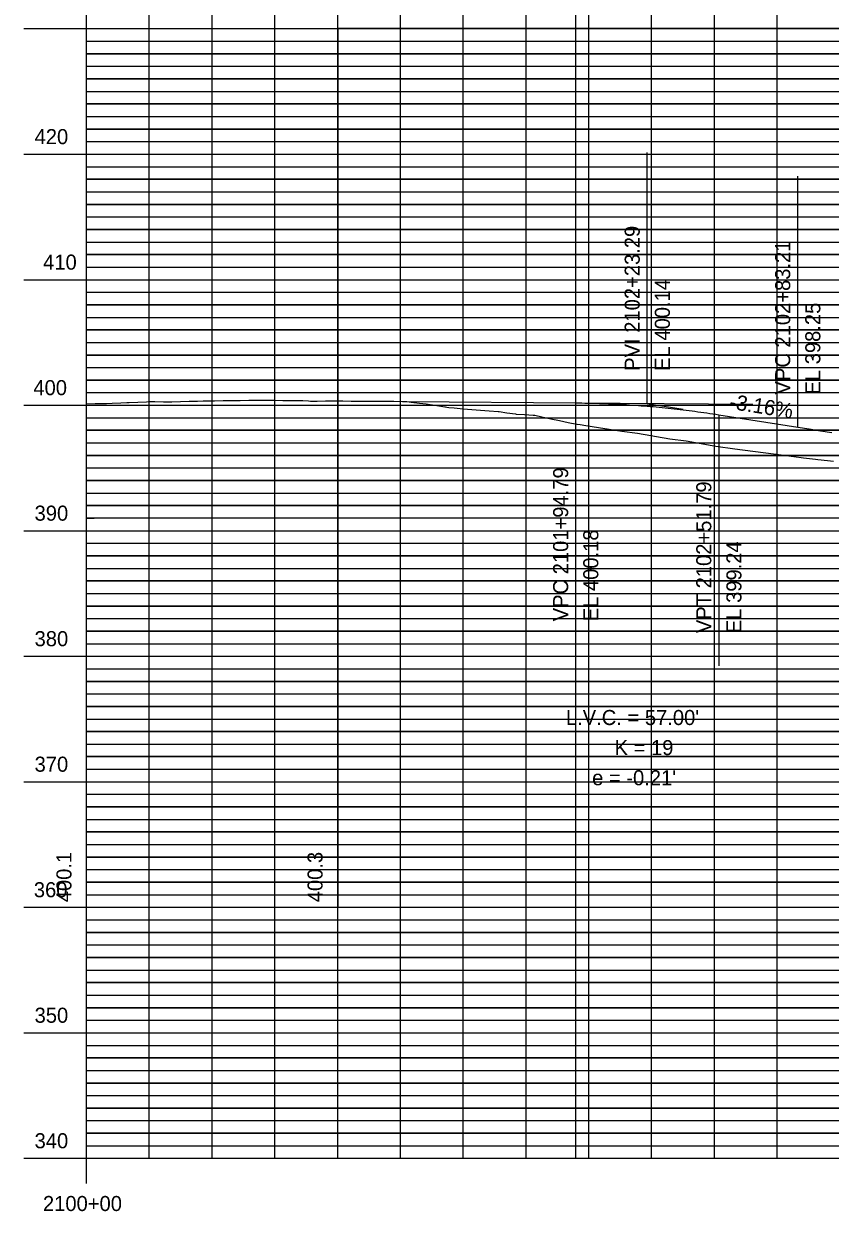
# Model space of a CAD drawing. Extents: x 1195880 to 1289360, y 2059330 to 2086925.
# Drawn here: x 1196947.8 to 1197268.9, y 2066770.1 to 2067243.1 of the extents above; entities that cross this region are included whole.
import ezdxf

# ---------------------------------------------------------------- set-up
doc = ezdxf.new("R2010")
doc.units = 0
for name, color, linetype in [('20', 7, 'Continuous'), ('41', 7, 'Continuous'), ('51', 7, 'Continuous'), ('Clip', 7, 'Continuous'), ('Default', 7, 'Continuous'), ('Existing Ground PGL', 7, 'Continuous'), ('Grid', 7, 'Continuous'), ('Grid Lables', 7, 'Continuous'), ('Profile', 7, 'Continuous'), ('Profile Annotation', 7, 'Continuous')]:
    doc.layers.add(name, color=color, linetype=linetype)

msp = doc.modelspace()

# ---------------------------------------------------------------- linework, layer by layer
at = {"layer": '20'}
msp.add_line((1197167.59, 2067092.07), (1197238.09, 2067091.52), dxfattribs=at)
at = {"layer": 'Clip'}
msp.add_lwpolyline([(1197072.8, 2066891.15), (1197672.8, 2066891.15), (1197672.8, 2067241.15), (1197072.8, 2067241.15)], close=True, dxfattribs=at)
at = {"layer": 'Default'}
for p, q in [((1197167.59, 2066791.15), (1197167.59, 2067423.97)), ((1196972.8, 2066791.15), (1197167.59, 2066791.15))]:
    msp.add_line(p, q, dxfattribs=at)
at = {"layer": 'Existing Ground PGL'}
msp.add_lwpolyline([(1196972.8, 2067091.71), (1196976.2, 2067091.78), (1196979.6, 2067091.82), (1196980.73, 2067091.84), (1196983, 2067091.96), (1196986.4, 2067092.12), (1196988.89, 2067092.24), (1196989.8, 2067092.28), (1196993.21, 2067092.42), (1196996.61, 2067092.55), (1196997.74, 2067092.58), (1197000.01, 2067092.57), (1197003.41, 2067092.54), (1197006.28, 2067092.51), (1197006.81, 2067092.53), (1197010.21, 2067092.65), (1197013.61, 2067092.76), (1197013.91, 2067092.77), (1197017.01, 2067092.82), (1197019.22, 2067092.85), (1197020.41, 2067092.88), (1197023.81, 2067092.96), (1197027.21, 2067093.03), (1197027.43, 2067093.03), (1197030.61, 2067093.05), (1197032.11, 2067093.06), (1197034.02, 2067093.08), (1197037.42, 2067093.11), (1197040.82, 2067093.12), (1197041.76, 2067093.12), (1197044.22, 2067093.11), (1197045.45, 2067093.1), (1197047.62, 2067093.1), (1197051.02, 2067093.08), (1197054.42, 2067093.06), (1197056.61, 2067093.04), (1197057.82, 2067093.02), (1197058.93, 2067093), (1197061.22, 2067092.86), (1197062.02, 2067092.8), (1197064.62, 2067092.82), (1197068.02, 2067092.83), (1197071.43, 2067092.83), (1197074.83, 2067092.83), (1197078.23, 2067092.82), (1197079.3, 2067092.81), (1197080.27, 2067092.81), (1197081.63, 2067092.81), (1197085.03, 2067092.79), (1197088.43, 2067092.76), (1197091.83, 2067092.73), (1197095.23, 2067092.7), (1197098.63, 2067092.65), (1197099.67, 2067092.64), (1197099.96, 2067092.62), (1197100.37, 2067092.61), (1197102.03, 2067092.41), (1197105.43, 2067092), (1197108.05, 2067091.67), (1197108.83, 2067091.55), (1197112.24, 2067091.03), (1197115.48, 2067090.54), (1197115.73, 2067090.5), (1197116.26, 2067090.43), (1197117.11, 2067090.29), (1197119.22, 2067090.09), (1197122.71, 2067089.76), (1197126.2, 2067089.44), (1197129.68, 2067089.14), (1197129.69, 2067089.14), (1197133.18, 2067088.89), (1197136.67, 2067088.65), (1197137.07, 2067088.63), (1197140.17, 2067088.18), (1197143.66, 2067087.69), (1197143.94, 2067087.65), (1197147.15, 2067087.42), (1197150.64, 2067087.19), (1197151.34, 2067087.15), (1197154.13, 2067086.52), (1197157.62, 2067085.77), (1197161.11, 2067085.03), (1197164.61, 2067084.32), (1197168.1, 2067083.62), (1197168.14, 2067083.62), (1197169.43, 2067083.47), (1197171.59, 2067083.12), (1197186.01, 2067080.83), (1197192.22, 2067080.08), (1197205.08, 2067077.78), (1197211.54, 2067076.92), (1197223.38, 2067074.86), (1197230.9, 2067073.84), (1197238.13, 2067072.87), (1197247.44, 2067071.65), (1197253.42, 2067070.85), (1197254.49, 2067070.71), (1197258.24, 2067070.23), (1197263.06, 2067069.66), (1197263.97, 2067069.55), (1197267.87, 2067069.12), (1197270.26, 2067068.88)], dxfattribs=at)
at = {"layer": 'Grid'}
for p, q in [((1196972.8, 2066791.15), (1196972.8, 2067391.15)), ((1196997.8, 2066791.15), (1196997.8, 2067391.15)), ((1197022.8, 2066791.15), (1197022.8, 2067391.15)), ((1197047.8, 2066791.15), (1197047.8, 2067391.15)), ((1197072.8, 2066791.15), (1197072.8, 2067391.15)), ((1197097.8, 2066791.15), (1197097.8, 2067391.15)), ((1197122.8, 2066791.15), (1197122.8, 2067391.15)), ((1197147.8, 2066791.15), (1197147.8, 2067391.15)), ((1197172.8, 2066791.15), (1197172.8, 2067391.15)), ((1197197.8, 2066791.15), (1197197.8, 2067391.15)), ((1197222.8, 2066791.15), (1197222.8, 2067391.15)), ((1197247.8, 2066791.15), (1197247.8, 2067391.15)), ((1196947.8, 2067241.15), (1196972.8, 2067241.15)), ((1196972.8, 2067241.15), (1197972.8, 2067241.15)), ((1196972.8, 2067236.15), (1196975.8, 2067236.15)), ((1196972.8, 2067236.15), (1197972.8, 2067236.15)), ((1196972.8, 2067231.15), (1196975.8, 2067231.15)), ((1196972.8, 2067231.15), (1197972.8, 2067231.15)), ((1197972.8, 2067231.15), (1196972.8, 2067231.15)), ((1196972.8, 2067226.15), (1196975.8, 2067226.15)), ((1196972.8, 2067226.15), (1197972.8, 2067226.15)), ((1196972.8, 2067221.15), (1196975.8, 2067221.15)), ((1196972.8, 2067221.15), (1197972.8, 2067221.15)), ((1197972.8, 2067221.15), (1196972.8, 2067221.15)), ((1196972.8, 2067216.15), (1196975.8, 2067216.15)), ((1196972.8, 2067216.15), (1197972.8, 2067216.15)), ((1196972.8, 2067211.15), (1196975.8, 2067211.15)), ((1196972.8, 2067211.15), (1197972.8, 2067211.15)), ((1197972.8, 2067211.15), (1196972.8, 2067211.15)), ((1196972.8, 2067206.15), (1196975.8, 2067206.15)), ((1196972.8, 2067206.15), (1197972.8, 2067206.15)), ((1196972.8, 2067201.15), (1196975.8, 2067201.15)), ((1196972.8, 2067201.15), (1197972.8, 2067201.15)), ((1197972.8, 2067201.15), (1196972.8, 2067201.15)), ((1196972.8, 2067196.15), (1196975.8, 2067196.15)), ((1196972.8, 2067196.15), (1197972.8, 2067196.15)), ((1196947.8, 2067191.15), (1196972.8, 2067191.15)), ((1196972.8, 2067191.15), (1197972.8, 2067191.15)), ((1196972.8, 2067186.15), (1196975.8, 2067186.15)), ((1196972.8, 2067186.15), (1197972.8, 2067186.15)), ((1196972.8, 2067181.15), (1196975.8, 2067181.15)), ((1196972.8, 2067181.15), (1197972.8, 2067181.15)), ((1197972.8, 2067181.15), (1196972.8, 2067181.15)), ((1196972.8, 2067176.15), (1196975.8, 2067176.15)), ((1196972.8, 2067176.15), (1197972.8, 2067176.15)), ((1196972.8, 2067171.15), (1196975.8, 2067171.15)), ((1196972.8, 2067171.15), (1197972.8, 2067171.15)), ((1197972.8, 2067171.15), (1196972.8, 2067171.15)), ((1196972.8, 2067166.15), (1196975.8, 2067166.15)), ((1196972.8, 2067166.15), (1197972.8, 2067166.15)), ((1196972.8, 2067161.15), (1196975.8, 2067161.15)), ((1196972.8, 2067161.15), (1197972.8, 2067161.15)), ((1197972.8, 2067161.15), (1196972.8, 2067161.15)), ((1196972.8, 2067156.15), (1196975.8, 2067156.15)), ((1196972.8, 2067156.15), (1197972.8, 2067156.15)), ((1196972.8, 2067151.15), (1196975.8, 2067151.15)), ((1196972.8, 2067151.15), (1197972.8, 2067151.15)), ((1197972.8, 2067151.15), (1196972.8, 2067151.15)), ((1196972.8, 2067146.15), (1196975.8, 2067146.15)), ((1196972.8, 2067146.15), (1197972.8, 2067146.15)), ((1196947.8, 2067141.15), (1196972.8, 2067141.15)), ((1196972.8, 2067141.15), (1197972.8, 2067141.15)), ((1196972.8, 2067136.15), (1196975.8, 2067136.15)), ((1196972.8, 2067136.15), (1197972.8, 2067136.15)), ((1196972.8, 2067131.15), (1196975.8, 2067131.15)), ((1196972.8, 2067131.15), (1197972.8, 2067131.15)), ((1197972.8, 2067131.15), (1196972.8, 2067131.15)), ((1196972.8, 2067126.15), (1196975.8, 2067126.15)), ((1196972.8, 2067126.15), (1197972.8, 2067126.15)), ((1196972.8, 2067121.15), (1196975.8, 2067121.15)), ((1196972.8, 2067121.15), (1197972.8, 2067121.15)), ((1197972.8, 2067121.15), (1196972.8, 2067121.15)), ((1196972.8, 2067116.15), (1196975.8, 2067116.15)), ((1196972.8, 2067116.15), (1197972.8, 2067116.15)), ((1196972.8, 2067111.15), (1196975.8, 2067111.15)), ((1196972.8, 2067111.15), (1197972.8, 2067111.15)), ((1197972.8, 2067111.15), (1196972.8, 2067111.15)), ((1196972.8, 2067106.15), (1196975.8, 2067106.15)), ((1196972.8, 2067106.15), (1197972.8, 2067106.15)), ((1196972.8, 2067101.15), (1196975.8, 2067101.15)), ((1196972.8, 2067101.15), (1197972.8, 2067101.15)), ((1197972.8, 2067101.15), (1196972.8, 2067101.15)), ((1196972.8, 2067096.15), (1196975.8, 2067096.15)), ((1196972.8, 2067096.15), (1197972.8, 2067096.15)), ((1196947.8, 2067091.15), (1196972.8, 2067091.15)), ((1196972.8, 2067091.15), (1197972.8, 2067091.15)), ((1196972.8, 2067086.15), (1196975.8, 2067086.15)), ((1196972.8, 2067086.15), (1197972.8, 2067086.15)), ((1196972.8, 2067081.15), (1196975.8, 2067081.15)), ((1196972.8, 2067081.15), (1197972.8, 2067081.15)), ((1197972.8, 2067081.15), (1196972.8, 2067081.15)), ((1196972.8, 2067076.15), (1196975.8, 2067076.15)), ((1196972.8, 2067076.15), (1197972.8, 2067076.15)), ((1196972.8, 2067071.15), (1196975.8, 2067071.15)), ((1196972.8, 2067071.15), (1197972.8, 2067071.15)), ((1197972.8, 2067071.15), (1196972.8, 2067071.15)), ((1196972.8, 2067066.15), (1196975.8, 2067066.15)), ((1196972.8, 2067066.15), (1197972.8, 2067066.15)), ((1196972.8, 2067061.15), (1196975.8, 2067061.15)), ((1196972.8, 2067061.15), (1197972.8, 2067061.15)), ((1197972.8, 2067061.15), (1196972.8, 2067061.15)), ((1196972.8, 2067056.15), (1196975.8, 2067056.15)), ((1196972.8, 2067056.15), (1197972.8, 2067056.15)), ((1196972.8, 2067051.15), (1196975.8, 2067051.15)), ((1196972.8, 2067051.15), (1197972.8, 2067051.15)), ((1197972.8, 2067051.15), (1196972.8, 2067051.15)), ((1196972.8, 2067046.15), (1196975.8, 2067046.15)), ((1197972.8, 2067046.15), (1196972.8, 2067046.15)), ((1196947.8, 2067041.15), (1196972.8, 2067041.15)), ((1196972.8, 2067041.15), (1197972.8, 2067041.15)), ((1196972.8, 2067036.15), (1196975.8, 2067036.15)), ((1196972.8, 2067036.15), (1197972.8, 2067036.15)), ((1196972.8, 2067031.15), (1196975.8, 2067031.15)), ((1196972.8, 2067031.15), (1197972.8, 2067031.15)), ((1197972.8, 2067031.15), (1196972.8, 2067031.15)), ((1196972.8, 2067026.15), (1196975.8, 2067026.15)), ((1196972.8, 2067026.15), (1197972.8, 2067026.15)), ((1196972.8, 2067021.15), (1196975.8, 2067021.15)), ((1196972.8, 2067021.15), (1197972.8, 2067021.15)), ((1197972.8, 2067021.15), (1196972.8, 2067021.15)), ((1196972.8, 2067016.15), (1196975.8, 2067016.15)), ((1196972.8, 2067016.15), (1197972.8, 2067016.15)), ((1196972.8, 2067011.15), (1196975.8, 2067011.15)), ((1196972.8, 2067011.15), (1197972.8, 2067011.15)), ((1197972.8, 2067011.15), (1196972.8, 2067011.15)), ((1196972.8, 2067006.15), (1196975.8, 2067006.15)), ((1196972.8, 2067006.15), (1197972.8, 2067006.15)), ((1196972.8, 2067001.15), (1196975.8, 2067001.15)), ((1196972.8, 2067001.15), (1197972.8, 2067001.15)), ((1197972.8, 2067001.15), (1196972.8, 2067001.15)), ((1196972.8, 2066996.15), (1196975.8, 2066996.15)), ((1196972.8, 2066996.15), (1197972.8, 2066996.15)), ((1196947.8, 2066991.15), (1196972.8, 2066991.15)), ((1196972.8, 2066991.15), (1197972.8, 2066991.15)), ((1196972.8, 2066986.15), (1196975.8, 2066986.15)), ((1196972.8, 2066986.15), (1197972.8, 2066986.15)), ((1196972.8, 2066981.15), (1196975.8, 2066981.15)), ((1196972.8, 2066981.15), (1197972.8, 2066981.15)), ((1197972.8, 2066981.15), (1196972.8, 2066981.15)), ((1196972.8, 2066976.15), (1196975.8, 2066976.15)), ((1196972.8, 2066976.15), (1197972.8, 2066976.15)), ((1196972.8, 2066971.15), (1196975.8, 2066971.15)), ((1196972.8, 2066971.15), (1197972.8, 2066971.15)), ((1197972.8, 2066971.15), (1196972.8, 2066971.15)), ((1196972.8, 2066966.15), (1196975.8, 2066966.15)), ((1196972.8, 2066966.15), (1197972.8, 2066966.15)), ((1196972.8, 2066961.15), (1196975.8, 2066961.15)), ((1196972.8, 2066961.15), (1197972.8, 2066961.15)), ((1197972.8, 2066961.15), (1196972.8, 2066961.15)), ((1196972.8, 2066956.15), (1196975.8, 2066956.15)), ((1196972.8, 2066956.15), (1197972.8, 2066956.15)), ((1196972.8, 2066951.15), (1196975.8, 2066951.15)), ((1196972.8, 2066951.15), (1197972.8, 2066951.15)), ((1197972.8, 2066951.15), (1196972.8, 2066951.15)), ((1196972.8, 2066946.15), (1196975.8, 2066946.15)), ((1196972.8, 2066946.15), (1197972.8, 2066946.15)), ((1196947.8, 2066941.15), (1196972.8, 2066941.15)), ((1196972.8, 2066941.15), (1197972.8, 2066941.15)), ((1196972.8, 2066936.15), (1196975.8, 2066936.15)), ((1196972.8, 2066936.15), (1197972.8, 2066936.15)), ((1196972.8, 2066931.15), (1196975.8, 2066931.15)), ((1196972.8, 2066931.15), (1197972.8, 2066931.15)), ((1197972.8, 2066931.15), (1196972.8, 2066931.15)), ((1196972.8, 2066926.15), (1196975.8, 2066926.15)), ((1196972.8, 2066926.15), (1197972.8, 2066926.15)), ((1196972.8, 2066921.15), (1196975.8, 2066921.15)), ((1196972.8, 2066921.15), (1197972.8, 2066921.15)), ((1197972.8, 2066921.15), (1196972.8, 2066921.15)), ((1196972.8, 2066916.15), (1196975.8, 2066916.15)), ((1196972.8, 2066916.15), (1197972.8, 2066916.15)), ((1196972.8, 2066911.15), (1196975.8, 2066911.15)), ((1196972.8, 2066911.15), (1197972.8, 2066911.15)), ((1197972.8, 2066911.15), (1196972.8, 2066911.15)), ((1196972.8, 2066906.15), (1196975.8, 2066906.15)), ((1196972.8, 2066906.15), (1197972.8, 2066906.15)), ((1196972.8, 2066901.15), (1196975.8, 2066901.15)), ((1196972.8, 2066901.15), (1197972.8, 2066901.15)), ((1197972.8, 2066901.15), (1196972.8, 2066901.15)), ((1196972.8, 2066896.15), (1196975.8, 2066896.15)), ((1196972.8, 2066896.15), (1197972.8, 2066896.15)), ((1196947.8, 2066891.15), (1196972.8, 2066891.15)), ((1196972.8, 2066891.15), (1197972.8, 2066891.15)), ((1196972.8, 2066886.15), (1196975.8, 2066886.15)), ((1196972.8, 2066886.15), (1197972.8, 2066886.15)), ((1196972.8, 2066881.15), (1196975.8, 2066881.15)), ((1196972.8, 2066881.15), (1197972.8, 2066881.15)), ((1197972.8, 2066881.15), (1196972.8, 2066881.15)), ((1196972.8, 2066876.15), (1196975.8, 2066876.15)), ((1196972.8, 2066876.15), (1197972.8, 2066876.15)), ((1196972.8, 2066871.15), (1196975.8, 2066871.15)), ((1196972.8, 2066871.15), (1197972.8, 2066871.15)), ((1197972.8, 2066871.15), (1196972.8, 2066871.15)), ((1196972.8, 2066866.15), (1196975.8, 2066866.15)), ((1196972.8, 2066866.15), (1197972.8, 2066866.15)), ((1196972.8, 2066861.15), (1196975.8, 2066861.15)), ((1196972.8, 2066861.15), (1197972.8, 2066861.15)), ((1197972.8, 2066861.15), (1196972.8, 2066861.15)), ((1196972.8, 2066856.15), (1196975.8, 2066856.15)), ((1196972.8, 2066856.15), (1197972.8, 2066856.15)), ((1196972.8, 2066851.15), (1196975.8, 2066851.15)), ((1196972.8, 2066851.15), (1197972.8, 2066851.15)), ((1197972.8, 2066851.15), (1196972.8, 2066851.15)), ((1196972.8, 2066846.15), (1196975.8, 2066846.15)), ((1196972.8, 2066846.15), (1197972.8, 2066846.15)), ((1196947.8, 2066841.15), (1196972.8, 2066841.15)), ((1196972.8, 2066841.15), (1197972.8, 2066841.15)), ((1196972.8, 2066836.15), (1196975.8, 2066836.15)), ((1196972.8, 2066836.15), (1197972.8, 2066836.15)), ((1196972.8, 2066831.15), (1196975.8, 2066831.15)), ((1196972.8, 2066831.15), (1197972.8, 2066831.15)), ((1197972.8, 2066831.15), (1196972.8, 2066831.15)), ((1196972.8, 2066826.15), (1196975.8, 2066826.15)), ((1196972.8, 2066826.15), (1197972.8, 2066826.15)), ((1196972.8, 2066821.15), (1196975.8, 2066821.15)), ((1196972.8, 2066821.15), (1197972.8, 2066821.15)), ((1197972.8, 2066821.15), (1196972.8, 2066821.15)), ((1196972.8, 2066816.15), (1196975.8, 2066816.15)), ((1196972.8, 2066816.15), (1197972.8, 2066816.15)), ((1196972.8, 2066811.15), (1196975.8, 2066811.15)), ((1196972.8, 2066811.15), (1197972.8, 2066811.15)), ((1197972.8, 2066811.15), (1196972.8, 2066811.15)), ((1196972.8, 2066806.15), (1196975.8, 2066806.15)), ((1196972.8, 2066806.15), (1197972.8, 2066806.15)), ((1196972.8, 2066801.15), (1196975.8, 2066801.15)), ((1196972.8, 2066801.15), (1197972.8, 2066801.15)), ((1197972.8, 2066801.15), (1196972.8, 2066801.15)), ((1196972.8, 2066796.15), (1196975.8, 2066796.15)), ((1196972.8, 2066796.15), (1197972.8, 2066796.15)), ((1196997.8, 2066791.15), (1196997.8, 2066794.15)), ((1197022.8, 2066791.15), (1197022.8, 2066794.15)), ((1197047.8, 2066791.15), (1197047.8, 2066794.15)), ((1197072.8, 2066791.15), (1197072.8, 2066794.15)), ((1197097.8, 2066791.15), (1197097.8, 2066794.15)), ((1197122.8, 2066791.15), (1197122.8, 2066794.15)), ((1197147.8, 2066791.15), (1197147.8, 2066794.15)), ((1197172.8, 2066791.15), (1197172.8, 2066794.15)), ((1197197.8, 2066791.15), (1197197.8, 2066794.15)), ((1197222.8, 2066791.15), (1197222.8, 2066794.15)), ((1197247.8, 2066791.15), (1197247.8, 2066794.15)), ((1196947.8, 2066791.15), (1196972.8, 2066791.15)), ((1196972.8, 2066791.15), (1197972.8, 2066791.15)), ((1196972.8, 2066781.15), (1196972.8, 2066791.15))]:
    msp.add_line(p, q, dxfattribs=at)
at = {"layer": 'Profile'}
for p, q in [((1197100.37, 2067092.61), (1197167.59, 2067092.07)), ((1197224.59, 2067087.35), (1197256.01, 2067082.4)), ((1197167.59, 2066992.07), (1197167.59, 2066992.07))]:
    msp.add_line(p, q, dxfattribs=at)
for points in [[(1197167.59, 2067092.07), (1197168.78, 2067092.06), (1197169.97, 2067092.05), (1197171.16, 2067092.03), (1197172.34, 2067092.01), (1197173.53, 2067091.98), (1197174.72, 2067091.95), (1197175.91, 2067091.92), (1197177.09, 2067091.88), (1197178.28, 2067091.84), (1197179.47, 2067091.79), (1197180.66, 2067091.75), (1197181.84, 2067091.69), (1197183.03, 2067091.64), (1197184.22, 2067091.58), (1197185.41, 2067091.52), (1197186.59, 2067091.45), (1197187.78, 2067091.38), (1197188.97, 2067091.3), (1197190.16, 2067091.23), (1197191.34, 2067091.14), (1197192.53, 2067091.06), (1197193.72, 2067090.97), (1197194.91, 2067090.88), (1197197.28, 2067090.68), (1197198.47, 2067090.58), (1197199.66, 2067090.47), (1197200.84, 2067090.36), (1197202.03, 2067090.24), (1197203.22, 2067090.12), (1197204.41, 2067090), (1197205.59, 2067089.88), (1197206.78, 2067089.75), (1197207.97, 2067089.61), (1197209.16, 2067089.47), (1197210.34, 2067089.33), (1197211.53, 2067089.19), (1197212.72, 2067089.04), (1197213.91, 2067088.89), (1197215.09, 2067088.73), (1197216.28, 2067088.57), (1197217.47, 2067088.41), (1197218.66, 2067088.24), (1197219.84, 2067088.07), (1197221.03, 2067087.9), (1197222.22, 2067087.72), (1197223.41, 2067087.54), (1197224.59, 2067087.35)], [(1197256.01, 2067082.4), (1197260.53, 2067081.69), (1197265.05, 2067080.99), (1197269.57, 2067080.31)]]:
    msp.add_lwpolyline(points, dxfattribs=at)
at = {"layer": 'Profile Annotation'}
for p, q in [((1197196.09, 2067091.85), (1197196.09, 2067191.85)), ((1197256.01, 2067082.4), (1197256.01, 2067182.4)), ((1197167.59, 2066992.07), (1197167.59, 2067092.07)), ((1197181.84, 2067091.96), (1197196.09, 2067091.85)), ((1197196.09, 2067091.85), (1197210.34, 2067089.6)), ((1197224.59, 2067087.35), (1197224.59, 2066987.35))]:
    msp.add_line(p, q, dxfattribs=at)

# ---------------------------------------------------------------- texts
at = {"layer": '41'}
for s, p in [('400.1', (1196966.8, 2066893.15)), ('400.3', (1197066.8, 2066893.15))]:
    msp.add_text(s, height=6, rotation=90, dxfattribs=at).set_placement(p)
at = {"layer": '51'}
msp.add_text('-', height=0.0001, dxfattribs=at).set_placement((1196972.8, 2066791.15))
at = {"layer": 'Grid Lables'}
for s, p in [('420', (1196952.11, 2067195.15)), ('410', (1196955.51, 2067145.15)), ('400', (1196951.63, 2067095.15)), ('390', (1196952.11, 2067045.15)), ('380', (1196952.11, 2066995.15)), ('370', (1196952.11, 2066945.15)), ('360', (1196951.82, 2066895.15)), ('350', (1196952.11, 2066845.15)), ('340', (1196952.11, 2066795.15)), ('2100+00', (1196955.44, 2066770.15))]:
    msp.add_text(s, height=6, dxfattribs=at).set_placement(p)
at = {"layer": 'Profile Annotation'}
for s, rotation, p in [('PVI 2102+23.29', 90, (1197193.09, 2067104.85)), ('VPC 2102+83.21', 90, (1197253.01, 2067095.4)), ('EL 400.14', 90, (1197205.09, 2067104.85)), ('EL 398.25', 90, (1197265.01, 2067095.4)), ('-3.16%', 351.0341, (1197228.52, 2067089.77)), ('VPC 2101+94.79', 90, (1197164.59, 2067005.07)), ('VPT 2102+51.79', 90, (1197221.59, 2067000.35)), ('EL 400.18', 90, (1197176.59, 2067005.07)), ('EL 399.24', 90, (1197233.59, 2067000.35))]:
    msp.add_text(s, height=6, rotation=rotation, dxfattribs=at).set_placement(p)
for s, p in [("L.V.C. = 57.00'", (1197163.69, 2066963.75)), ('K = 19', (1197183.08, 2066951.75)), ("e = -0.21'", (1197174.13, 2066939.75))]:
    msp.add_text(s, height=6, dxfattribs=at).set_placement(p)

doc.saveas('drawing.dxf')
